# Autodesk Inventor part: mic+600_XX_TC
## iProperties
Shininess: 20.0
Length Units: 11269
Angle Units: 11279
Time Units: 11290
Mass Units: 11283
Length Display Precision: 2
Angle Display Precision: 2
Company: Microsonic
Part Number: mic+600_XX_TC
Material: ABS Plastik
Document SubType Name: Modellieren
Description: mic+ 600 Sensor
Checked By: Alves
Created: 2005-08
Designer: Ohle
Manufacturer: Standard
Standards Organization: Custom
Density: 0.0
Volumn: 0.0
Area: 0.0
PropertySet Name: Model Information
Control State: 0
Master: False
Checked Out: False
BESTELLNUMMER: mic+600/XX/TC
ME: ST
Title: mic+ 25 Sensor
Author: Ohle
Comments: keine Bemerkung
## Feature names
1. Grundkörper [Revolution]
2. Messkopf mic+600 [Revolution]
3. Bohrung1 [Hole]
4. Pole [Extrusion]
5. Abrundung Pole [Fillet]
6. Verdrehsicherung [Extrusion]
